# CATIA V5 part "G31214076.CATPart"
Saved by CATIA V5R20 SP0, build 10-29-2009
Part number: G31214076
Revision: 3
Definition: design
Nomenclature: G31214076
Source: made
Description: NOT SPECIFIED
Bounding box of the stored display mesh (mm): x -6 to 76, y -12.31 to 12.31, z -12.5 to 12.5
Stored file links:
  C:\Users\Raffaele\Desktop\3D X SITO CF\BOLEX\23-BUSH REF 312\G31214076.CATPart

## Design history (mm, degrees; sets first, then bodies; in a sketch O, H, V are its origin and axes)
Body1 "MANIFOLD_SOLID_BREP #16995" (main body)
  Solid1: solid without history
Body2 "MANIFOLD_SOLID_BREP #17138"
  Solid2: solid without history
Body3 "MANIFOLD_SOLID_BREP #17281"
  Solid3: solid without history
Body4 "MANIFOLD_SOLID_BREP #17424"
  Solid4: solid without history
Body5 "MANIFOLD_SOLID_BREP #17567"
  Solid5: solid without history
Body6 "MANIFOLD_SOLID_BREP #17712"
  Solid6: solid without history
Body7 "MANIFOLD_SOLID_BREP #17857"
  Solid7: solid without history
Body8 "MANIFOLD_SOLID_BREP #18002"
  Solid8: solid without history
Body9 "MANIFOLD_SOLID_BREP #18147"
  Solid9: solid without history
Body10 "MANIFOLD_SOLID_BREP #18292"
  Solid10: solid without history
Body11 "MANIFOLD_SOLID_BREP #18437"
  Solid11: solid without history
Body12 "MANIFOLD_SOLID_BREP #18582"
  Solid12: solid without history
Body13 "MANIFOLD_SOLID_BREP #18727"
  Solid13: solid without history
Body14 "MANIFOLD_SOLID_BREP #18872"
  Solid14: solid without history
Body15 "MANIFOLD_SOLID_BREP #19017"
  Solid15: solid without history
Body16 "MANIFOLD_SOLID_BREP #19162"
  Solid16: solid without history
Body17 "MANIFOLD_SOLID_BREP #19307"
  Solid17: solid without history
Body18 "MANIFOLD_SOLID_BREP #19452"
  Solid18: solid without history
Body19 "MANIFOLD_SOLID_BREP #19597"
  Solid19: solid without history
Body20 "MANIFOLD_SOLID_BREP #19742"
  Solid20: solid without history
Body21 "MANIFOLD_SOLID_BREP #19889"
  Solid21: solid without history
Body22 "MANIFOLD_SOLID_BREP #20034"
  Solid22: solid without history
Body23 "MANIFOLD_SOLID_BREP #20179"
  Solid23: solid without history
Body24 "MANIFOLD_SOLID_BREP #20326"
  Solid24: solid without history
Body25 "MANIFOLD_SOLID_BREP #20471"
  Solid25: solid without history
Body26 "MANIFOLD_SOLID_BREP #20616"
  Solid26: solid without history
Body27 "MANIFOLD_SOLID_BREP #20761"
  Solid27: solid without history
Body28 "MANIFOLD_SOLID_BREP #20906"
  Solid28: solid without history
Body29 "MANIFOLD_SOLID_BREP #21051"
  Solid29: solid without history
Body30 "MANIFOLD_SOLID_BREP #21196"
  Solid30: solid without history
Body31 "MANIFOLD_SOLID_BREP #21341"
  Solid31: solid without history
Body32 "MANIFOLD_SOLID_BREP #21484"
  Solid32: solid without history
Body33 "MANIFOLD_SOLID_BREP #21627"
  Solid33: solid without history
Body34 "MANIFOLD_SOLID_BREP #21772"
  Solid34: solid without history
Body35 "MANIFOLD_SOLID_BREP #21917"
  Solid35: solid without history
Body36 "MANIFOLD_SOLID_BREP #22062"
  Solid36: solid without history
Body37 "MANIFOLD_SOLID_BREP #22209"
  Solid37: solid without history
Body38 "MANIFOLD_SOLID_BREP #22354"
  Solid38: solid without history
Body39 "MANIFOLD_SOLID_BREP #22499"
  Solid39: solid without history
Body40 "MANIFOLD_SOLID_BREP #22646"
  Solid40: solid without history
Body41 "MANIFOLD_SOLID_BREP #22791"
  Solid41: solid without history
Body42 "MANIFOLD_SOLID_BREP #22936"
  Solid42: solid without history
Body43 "MANIFOLD_SOLID_BREP #23081"
  Solid43: solid without history
Body44 "MANIFOLD_SOLID_BREP #23226"
  Solid44: solid without history
Body45 "MANIFOLD_SOLID_BREP #23371"
  Solid45: solid without history
Body46 "MANIFOLD_SOLID_BREP #23516"
  Solid46: solid without history
Body47 "MANIFOLD_SOLID_BREP #23661"
  Solid47: solid without history
Body48 "MANIFOLD_SOLID_BREP #23806"
  Solid48: solid without history
Body49 "MANIFOLD_SOLID_BREP #23951"
  Solid49: solid without history
Body50 "MANIFOLD_SOLID_BREP #24096"
  Solid50: solid without history
Body51 "MANIFOLD_SOLID_BREP #24243"
  Solid51: solid without history
Body52 "MANIFOLD_SOLID_BREP #24388"
  Solid52: solid without history
Body53 "MANIFOLD_SOLID_BREP #24533"
  Solid53: solid without history
Body54 "MANIFOLD_SOLID_BREP #24680"
  Solid54: solid without history
Body55 "MANIFOLD_SOLID_BREP #24825"
  Solid55: solid without history
Body56 "MANIFOLD_SOLID_BREP #24968"
  Solid56: solid without history
Body57 "MANIFOLD_SOLID_BREP #25111"
  Solid57: solid without history
Body58 "MANIFOLD_SOLID_BREP #25256"
  Solid58: solid without history
Body59 "MANIFOLD_SOLID_BREP #25401"
  Solid59: solid without history
Body60 "MANIFOLD_SOLID_BREP #25546"
  Solid60: solid without history
Body61 "MANIFOLD_SOLID_BREP #25691"
  Solid61: solid without history
Body62 "MANIFOLD_SOLID_BREP #25836"
  Solid62: solid without history
Body63 "MANIFOLD_SOLID_BREP #25981"
  Solid63: solid without history
Body64 "MANIFOLD_SOLID_BREP #26124"
  Solid64: solid without history
Body65 "MANIFOLD_SOLID_BREP #26267"
  Solid65: solid without history
Body66 "MANIFOLD_SOLID_BREP #26412"
  Solid66: solid without history
Body67 "MANIFOLD_SOLID_BREP #26557"
  Solid67: solid without history
Body68 "MANIFOLD_SOLID_BREP #26702"
  Solid68: solid without history
Body69 "MANIFOLD_SOLID_BREP #26849"
  Solid69: solid without history
Body70 "MANIFOLD_SOLID_BREP #26994"
  Solid70: solid without history
Body71 "MANIFOLD_SOLID_BREP #27139"
  Solid71: solid without history
Body72 "MANIFOLD_SOLID_BREP #27286"
  Solid72: solid without history
Body73 "MANIFOLD_SOLID_BREP #27431"
  Solid73: solid without history
Body74 "MANIFOLD_SOLID_BREP #27576"
  Solid74: solid without history
Body75 "MANIFOLD_SOLID_BREP #27721"
  Solid75: solid without history
Body76 "MANIFOLD_SOLID_BREP #27866"
  Solid76: solid without history
Body77 "MANIFOLD_SOLID_BREP #28011"
  Solid77: solid without history
Body78 "MANIFOLD_SOLID_BREP #28156"
  Solid78: solid without history
Body79 "MANIFOLD_SOLID_BREP #28301"
  Solid79: solid without history
Body80 "MANIFOLD_SOLID_BREP #28446"
  Solid80: solid without history
Body81 "MANIFOLD_SOLID_BREP #28591"
  Solid81: solid without history
Body82 "MANIFOLD_SOLID_BREP #28736"
  Solid82: solid without history
Body83 "MANIFOLD_SOLID_BREP #28883"
  Solid83: solid without history
Body84 "MANIFOLD_SOLID_BREP #29028"
  Solid84: solid without history
Body85 "MANIFOLD_SOLID_BREP #29173"
  Solid85: solid without history
Body86 "MANIFOLD_SOLID_BREP #29320"
  Solid86: solid without history
Body87 "MANIFOLD_SOLID_BREP #29465"
  Solid87: solid without history
Body88 "MANIFOLD_SOLID_BREP #29608"
  Solid88: solid without history
Body89 "MANIFOLD_SOLID_BREP #29751"
  Solid89: solid without history
Body90 "MANIFOLD_SOLID_BREP #29896"
  Solid90: solid without history
Body91 "MANIFOLD_SOLID_BREP #30041"
  Solid91: solid without history
Body92 "MANIFOLD_SOLID_BREP #30186"
  Solid92: solid without history
Body93 "MANIFOLD_SOLID_BREP #30331"
  Solid93: solid without history
Body94 "MANIFOLD_SOLID_BREP #30476"
  Solid94: solid without history
Body95 "MANIFOLD_SOLID_BREP #30621"
  Solid95: solid without history
Body96 "MANIFOLD_SOLID_BREP #30764"
  Solid96: solid without history
Body97 "MANIFOLD_SOLID_BREP #30907"
  Solid97: solid without history
Body98 "MANIFOLD_SOLID_BREP #31052"
  Solid98: solid without history
Body99 "MANIFOLD_SOLID_BREP #31197"
  Solid99: solid without history
Body100 "MANIFOLD_SOLID_BREP #31342"
  Solid100: solid without history
Body101 "MANIFOLD_SOLID_BREP #31489"
  Solid101: solid without history
Body102 "MANIFOLD_SOLID_BREP #31634"
  Solid102: solid without history
Body103 "MANIFOLD_SOLID_BREP #31779"
  Solid103: solid without history
Body104 "MANIFOLD_SOLID_BREP #31926"
  Solid104: solid without history
Body105 "MANIFOLD_SOLID_BREP #32071"
  Solid105: solid without history
Body106 "MANIFOLD_SOLID_BREP #32216"
  Solid106: solid without history
Body107 "MANIFOLD_SOLID_BREP #32361"
  Solid107: solid without history
Body108 "MANIFOLD_SOLID_BREP #32506"
  Solid108: solid without history
Body109 "MANIFOLD_SOLID_BREP #32651"
  Solid109: solid without history
Body110 "MANIFOLD_SOLID_BREP #32796"
  Solid110: solid without history
Body111 "MANIFOLD_SOLID_BREP #32941"
  Solid111: solid without history
Body112 "MANIFOLD_SOLID_BREP #33084"
  Solid112: solid without history
Body113 "MANIFOLD_SOLID_BREP #33227"
  Solid113: solid without history
Body114 "MANIFOLD_SOLID_BREP #33372"
  Solid114: solid without history
Body115 "MANIFOLD_SOLID_BREP #33517"
  Solid115: solid without history
Body116 "MANIFOLD_SOLID_BREP #33662"
  Solid116: solid without history
Body117 "MANIFOLD_SOLID_BREP #33809"
  Solid117: solid without history
Body118 "MANIFOLD_SOLID_BREP #33954"
  Solid118: solid without history
Body119 "MANIFOLD_SOLID_BREP #34099"
  Solid119: solid without history
Body120 "MANIFOLD_SOLID_BREP #34246"
  Solid120: solid without history
Body121 "MANIFOLD_SOLID_BREP #34391"
  Solid121: solid without history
